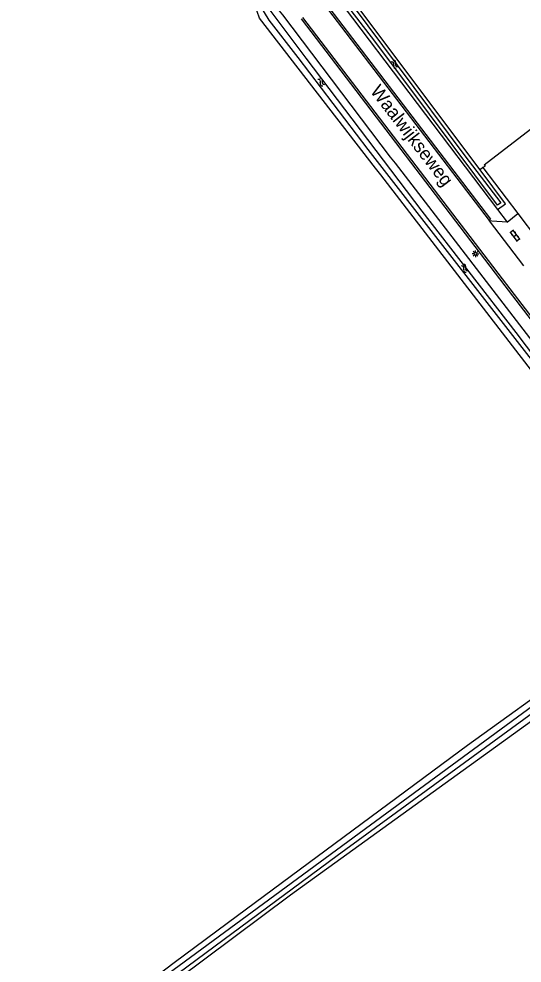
# Model space of a CAD drawing. Extents: x 136000 to 141000, y 400494 to 402006.
# Drawn here: x 136248.5 to 136343.1, y 401582.2 to 401759.9 of the extents above; entities that cross this region are included whole.
import ezdxf

# ---------------------------------------------------------------- set-up
doc = ezdxf.new("R2010")
doc.units = 0
for name, color, linetype in [('gg-afsc-draadraster', 7, 'Continuous'), ('gg-afsc-hekwerk', 7, 'Continuous'), ('gg-afsc-lijn draadraster', 7, 'Continuous'), ('gg-anno-openbare ruimte label', 7, 'Continuous'), ('gg-knt-verharding', 7, 'Continuous'), ('gg-kntw-bovenkant insteek waterloop', 7, 'Continuous'), ('gg-kntw-waterlijn', 7, 'Continuous'), ('gt-grn-groengrens', 7, 'Continuous'), ('gt-symb-klinker verharding', 7, 'Continuous'), ('gt-symb-lichtmast', 7, 'Continuous'), ('gt-symb-watersymbool', 7, 'Continuous')]:
    doc.layers.add(name, color=color, linetype=linetype)

# ---------------------------------------------------------------- blocks, each defined once
blk = doc.blocks.new('gt0-WA')
at = {"layer": 'gt-symb-watersymbool'}
for centre, start, end in [((-0.32, 0.02), 28.0725, 151.9275), ((0.43, 0.42), 208.0725, 331.9275), ((-0.32, -0.43), 28.0725, 151.9275), ((0.43, -0.03), 208.0725, 331.9275)]:
    blk.add_arc(centre, 0.425, start, end, dxfattribs=at)
blk = doc.blocks.new('gt0-KL1')
at = {"layer": 'gt-symb-klinker verharding'}
for p, q in [((-1.15, 0.3), (1.15, 0.3)), ((-1, -0.3), (-1, 0.3)), ((-0.5, 0.3), (-0.5, 0.45)), ((0, -0.3), (0, 0.3)), ((0.5, 0.3), (0.5, 0.45)), ((1, -0.3), (1, 0.3)), ((-1.15, -0.3), (1.15, -0.3)), ((-0.5, -0.45), (-0.5, -0.3)), ((0.5, -0.45), (0.5, -0.3))]:
    blk.add_line(p, q, dxfattribs=at)
blk = doc.blocks.new('gt0-LMAST')
at = {"layer": 'gt-symb-lichtmast'}
for p, q in [((-0.18, 0.17), (-0.45, 0.44)), ((-0.01, 0.25), (-0.01, 0.62)), ((0.17, 0.17), (0.44, 0.44)), ((-0.26, 0), (-0.63, 0)), ((-0.18, -0.18), (-0.45, -0.45)), ((-0.01, -0.25), (-0.01, -0.63)), ((0.44, -0.45), (0.17, -0.18)), ((0.24, 0), (0.62, 0))]:
    blk.add_line(p, q, dxfattribs=at)
blk.add_circle((-0.01, 0), 0.25, dxfattribs=at)

msp = doc.modelspace()

# ---------------------------------------------------------------- linework, layer by layer
at = {"layer": 'gg-afsc-draadraster'}
msp.add_lwpolyline([(136336.02, 401732.4), (136371.34, 401759.63), (136404.62, 401716.46)], dxfattribs=at)
at = {"layer": 'gg-afsc-hekwerk'}
for p, q in [((136336.16, 401732.2), (136335.77, 401731.9)), ((136335.77, 401731.9), (136342.33, 401723.25)), ((136342.33, 401723.25), (136346.05, 401718.35))]:
    msp.add_line(p, q, dxfattribs=at)
at = {"layer": 'gg-afsc-lijn draadraster'}
msp.add_lwpolyline([(136336.02, 401732.4), (136371.34, 401759.63), (136404.62, 401716.46)], dxfattribs=at)
at = {"layer": 'gg-knt-verharding'}
for p, q in [((136305.68, 401762.84), (136336.91, 401721.93)), ((136340.3, 401721.66), (136342.33, 401723.25)), ((136336.91, 401721.93), (136336.95, 401721.87)), ((136337.45, 401721.84), (136336.95, 401721.87)), ((136336.95, 401721.87), (136343.4, 401713.39)), ((136340.3, 401721.66), (136337.45, 401721.84))]:
    msp.add_line(p, q, dxfattribs=at)
for points in [[(136305.98, 401763.08), (136337.2, 401722.18), (136336.91, 401721.93)], [(136398.16, 401633.71), (136339.94, 401709.66), (136301.62, 401759.9)], [(136398.45, 401633.95), (136340.23, 401709.89), (136301.9, 401760.16)]]:
    msp.add_lwpolyline(points, dxfattribs=at)
at = {"layer": 'gg-kntw-bovenkant insteek waterloop'}
for p, q in [((136304.61, 401768.8), (136338.49, 401724.02)), ((136335.21, 401731.49), (136306.96, 401769.24)), ((136340.03, 401725.06), (136335.21, 401731.49)), ((136344.92, 401693.72), (136316.55, 401730.57)), ((136338.49, 401724.02), (136340.03, 401725.06))]:
    msp.add_line(p, q, dxfattribs=at)
for points in [[(136292.43, 401763.87), (136294.27, 401765.24), (136298.06, 401760.64), (136318.34, 401733.9)], [(136316.55, 401730.57), (136315.58, 401731.82), (136293.75, 401760.03), (136292.43, 401763.87)], [(136318.34, 401733.9), (136319.24, 401732.71), (136347.67, 401695.76), (136344.92, 401693.72)], [(136375.21, 401654.13), (136352.39, 401637.21), (136332.83, 401623.1), (136289.61, 401591.08), (136277.69, 401582.2), (136255.46, 401565.32), (136184.51, 401512.5), (136166.9, 401499.94)], [(136170.2, 401500), (136210.7, 401529.73), (136255.91, 401563.22), (136278.22, 401579.06), (136299.53, 401595), (136354.37, 401634.58), (136376.71, 401650.96)]]:
    msp.add_lwpolyline(points, dxfattribs=at)
at = {"layer": 'gg-kntw-waterlijn'}
for points in [[(136306, 401769.53), (136319.6, 401751.19), (136332.34, 401734.13), (136339.13, 401725.28), (136338.51, 401724.81), (136325.71, 401741.95), (136315.41, 401755.73), (136307.15, 401766.52), (136305.25, 401769.13)], [(136293.25, 401763.38), (136295.5, 401759.66), (136300.97, 401752.6), (136314.11, 401735.33), (136337.8, 401704.81), (136345.26, 401695.19), (136345.73, 401695.25), (136345.89, 401695.7), (136342.02, 401700.87), (136324.35, 401723.68), (136302.49, 401752.48), (136294.01, 401763.89), (136293.25, 401763.38)], [(136375.64, 401653.24), (136372.98, 401651.05), (136312.47, 401606.55), (136271.25, 401576.24), (136266.07, 401572.16), (136231.63, 401546.69), (136178.21, 401507.19), (136164.44, 401497.08)], [(136376.11, 401652.22), (136350.64, 401633.27), (136308.36, 401602.38), (136278.6, 401580.36), (136244.79, 401555.35), (136215.27, 401533.71), (136181.97, 401509.02), (136176.87, 401505.26), (136164.93, 401496.47)]]:
    msp.add_lwpolyline(points, dxfattribs=at)
at = {"layer": 'gt-grn-groengrens'}
for p, q in [((136335.77, 401731.9), (136335.21, 401731.49)), ((136336.02, 401732.4), (136336.16, 401732.2)), ((136338.49, 401724.02), (136340.3, 401721.66))]:
    msp.add_line(p, q, dxfattribs=at)

# ---------------------------------------------------------------- block references
at = {"layer": 'gt-symb-klinker verharding', "rotation": 126.95012773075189}
msp.add_blockref('gt0-KL1', (136341.81, 401719.08), dxfattribs=at)
at = {"layer": 'gt-symb-lichtmast'}
msp.add_blockref('gt0-LMAST', (136334.39, 401715.67), dxfattribs=at)
at = {"layer": 'gt-symb-watersymbool'}
for p, rotation in [((136319.13, 401751.39), -52.84362584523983), ((136305.32, 401748.08), -52.843625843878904), ((136332.31, 401712.99), -52.39646300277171)]:
    msp.add_blockref('gt0-WA', p, dxfattribs=dict(at, rotation=rotation))

# ---------------------------------------------------------------- texts
at = {"layer": 'gg-anno-openbare ruimte label'}
msp.add_text('Waalwijkseweg', height=2.5, rotation=307.6, dxfattribs=at).set_placement((136314.45, 401746.25))

doc.saveas('drawing.dxf')
